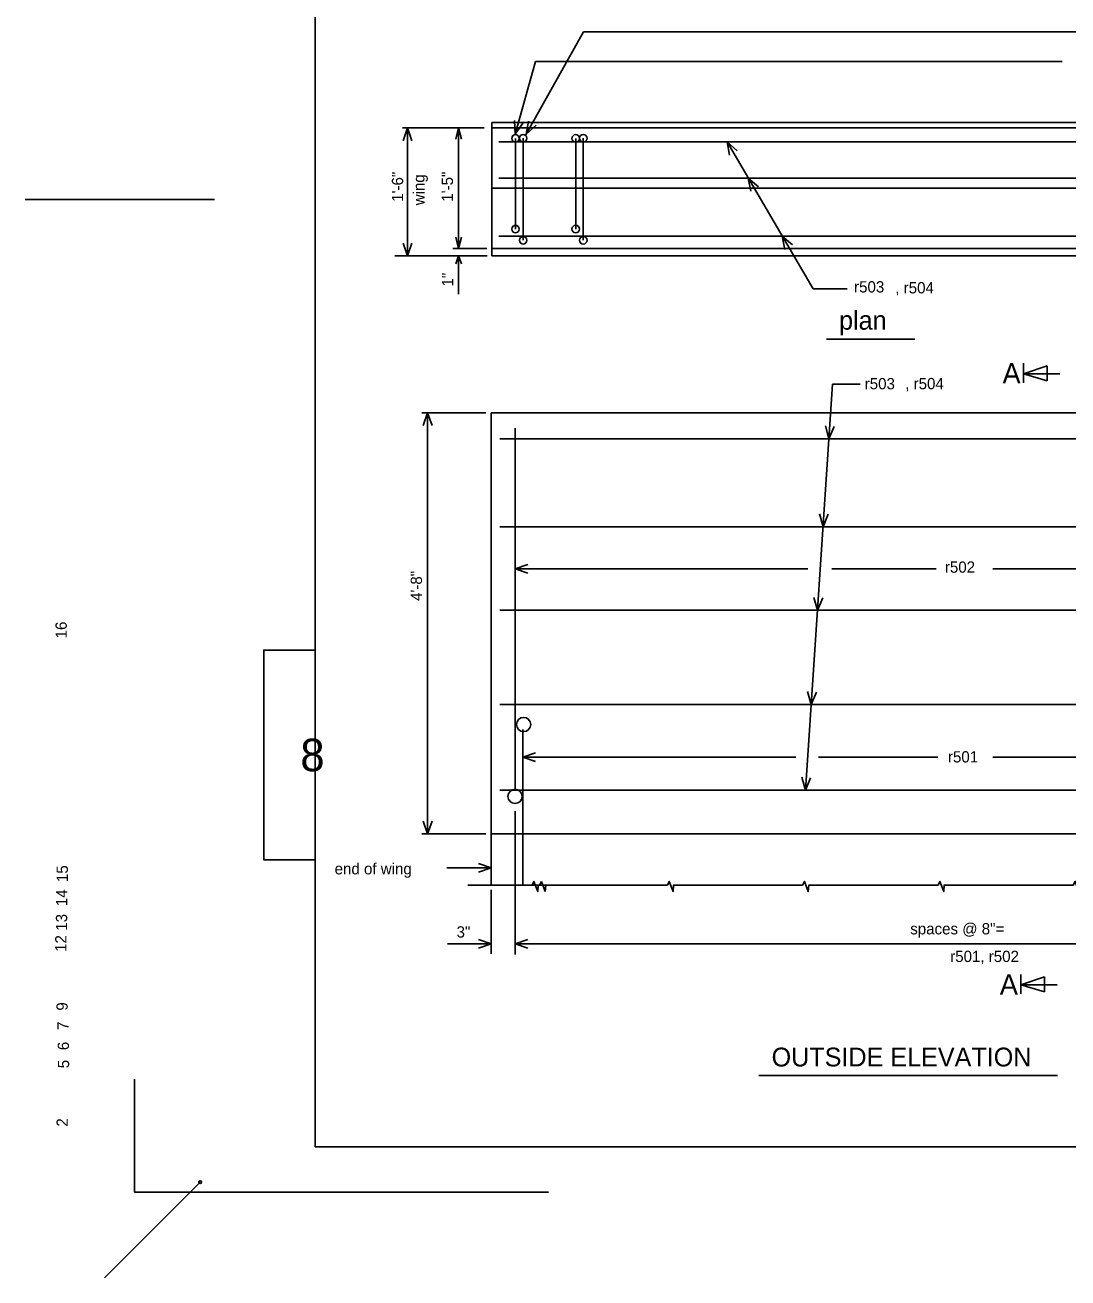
# Model space of a CAD drawing. Extents: x -81 to -44.8, y 85.9 to 111.1.
# Drawn here: x -81.01 to -69.45, y 86.74 to 100.62 of the extents above; entities that cross this region are included whole.
import ezdxf

# ---------------------------------------------------------------- set-up
doc = ezdxf.new("R2010")
doc.units = 0
for name, color, linetype in [('Level 1', 7, 'Continuous'), ('Level 12', 7, 'Continuous'), ('Level 13', 7, 'Continuous'), ('Level 14', 7, 'Continuous'), ('Level 15', 7, 'Continuous'), ('Level 16', 7, 'Continuous'), ('Level 2', 7, 'Continuous'), ('Level 37', 7, 'Continuous'), ('Level 49', 7, 'Continuous'), ('Level 5', 7, 'Continuous'), ('Level 6', 7, 'Continuous'), ('Level 7', 7, 'Continuous'), ('Level 9', 7, 'Continuous')]:
    doc.layers.add(name, color=color, linetype=linetype)

msp = doc.modelspace()

# ---------------------------------------------------------------- linework, layer by layer
at = {"layer": 'Level 1'}
for p, q in [((-77.797, 88.192), (-77.797, 109.192)), ((-76.156, 99.483), (-76.269, 99.483)), ((-76.206, 99.483), (-76.206, 98.149)), ((-75.895, 98.149), (-76.269, 98.149)), ((-79.797, 88.944), (-79.797, 87.692)), ((-77.797, 88.192), (-46.422, 88.192)), ((-79.797, 87.692), (-75.209, 87.692))]:
    msp.add_line(p, q, dxfattribs=at)
for points in [[(-76.238, 99.358), (-76.206, 99.483), (-76.175, 99.358)], [(-76.175, 98.274), (-76.206, 98.149), (-76.238, 98.274)]]:
    msp.add_lwpolyline(points, dxfattribs=at)
msp.add_lwpolyline([(-77.797, 93.697), (-78.365, 93.697), (-78.365, 91.375), (-77.797, 91.375)], close=True, dxfattribs=at)
at = {"layer": 'Level 2'}
for p, q in [((-76.206, 98.066), (-76.206, 97.642)), ((-80.129, 86.74), (-79.069, 87.801))]:
    msp.add_line(p, q, dxfattribs=at)
msp.add_lwpolyline([(-76.237, 97.978), (-76.206, 98.066), (-76.176, 97.978)], dxfattribs=at)
at = {"layer": 'Level 37'}
msp.add_line((-78.912, 98.692), (-81.011, 98.692), dxfattribs=at)
at = {"layer": 'Level 49'}
msp.add_circle((-79.069, 87.801), 0.0152, dxfattribs=at)
at = {"layer": 'Level 5'}
for p, q in [((-75.457, 99.413), (-74.821, 100.55)), ((-74.821, 100.55), (-69.231, 100.55)), ((-75.579, 99.416), (-75.355, 100.22)), ((-75.355, 100.22), (-75.092, 100.22)), ((-75.355, 100.22), (-69.518, 100.22)), ((-65.333, 99.545), (-75.839, 99.545)), ((-75.839, 98.149), (-75.839, 99.545)), ((-75.922, 99.483), (-76.829, 99.483)), ((-76.772, 98.066), (-76.772, 99.483)), ((-65.333, 99.483), (-75.839, 99.483)), ((-65.333, 99.328), (-75.762, 99.328)), ((-75.576, 99.368), (-75.576, 98.363)), ((-75.491, 99.369), (-75.491, 98.238)), ((-74.909, 99.368), (-74.909, 98.363)), ((-74.825, 99.369), (-74.825, 98.238)), ((-65.333, 98.928), (-75.762, 98.928)), ((-65.333, 98.816), (-75.839, 98.816)), ((-75.762, 98.284), (-65.333, 98.284)), ((-75.889, 98.066), (-76.913, 98.066)), ((-75.839, 98.066), (-75.839, 98.149)), ((-65.333, 98.149), (-75.839, 98.149)), ((-65.333, 98.066), (-75.839, 98.066)), ((-72.13, 97.143), (-71.152, 97.143)), ((-69.947, 96.876), (-69.947, 96.66)), ((-69.947, 96.759), (-69.683, 96.847)), ((-69.683, 96.847), (-69.683, 96.682)), ((-72.364, 92.144), (-72.062, 96.645)), ((-72.062, 96.645), (-71.756, 96.645)), ((-69.683, 96.682), (-69.947, 96.759)), ((-69.947, 96.759), (-69.543, 96.759)), ((-75.906, 96.328), (-76.612, 96.328)), ((-76.55, 96.328), (-76.55, 91.661)), ((-75.844, 96.328), (-75.844, 91.093)), ((-75.844, 96.328), (-65.352, 96.328)), ((-75.581, 96.155), (-75.581, 92.144)), ((-65.352, 96.039), (-75.749, 96.039)), ((-65.352, 95.065), (-75.749, 95.065)), ((-75.581, 94.597), (-72.335, 94.597)), ((-72.071, 94.597), (-70.914, 94.597)), ((-70.285, 94.597), (-65.352, 94.597)), ((-65.352, 94.138), (-75.749, 94.138)), ((-65.352, 93.095), (-75.749, 93.095)), ((-75.496, 92.816), (-75.496, 91.093)), ((-75.496, 92.51), (-72.468, 92.51)), ((-72.22, 92.51), (-70.897, 92.51)), ((-70.285, 92.51), (-65.352, 92.51)), ((-65.352, 92.144), (-75.749, 92.144)), ((-75.581, 91.911), (-75.581, 90.326)), ((-75.906, 91.661), (-76.612, 91.661)), ((-75.844, 91.661), (-65.352, 91.661)), ((-76.337, 91.284), (-75.844, 91.284)), ((-76.1, 91.093), (-75.309, 91.093)), ((-75.309, 91.093), (-75.288, 91.134)), ((-75.288, 91.134), (-75.246, 91.022)), ((-75.246, 91.022), (-75.24, 91.093)), ((-75.844, 91.042), (-75.844, 90.331)), ((-76.33, 90.443), (-75.844, 90.443)), ((-75.581, 90.443), (-64.05, 90.443)), ((-69.977, 90.104), (-69.977, 89.888)), ((-69.977, 89.987), (-69.714, 90.075)), ((-69.714, 89.91), (-69.977, 89.987)), ((-69.977, 89.987), (-69.573, 89.987)), ((-69.714, 90.075), (-69.714, 89.91)), ((-72.881, 88.983), (-69.57, 88.983)), ((-72.881, 88.983), (-69.57, 88.983))]:
    msp.add_line(p, q, dxfattribs=at)
for points in [[(-75.494, 99.538), (-75.579, 99.416), (-75.588, 99.565)], [(-75.346, 99.513), (-75.457, 99.413), (-75.431, 99.56)], [(-76.821, 99.342), (-76.772, 99.483), (-76.723, 99.342)], [(-73.232, 99.328), (-72.277, 97.7), (-71.901, 97.7)], [(-73.203, 99.181), (-73.232, 99.328), (-73.119, 99.231)], [(-72.968, 98.782), (-72.998, 98.928), (-72.884, 98.831)], [(-76.723, 98.207), (-76.772, 98.066), (-76.821, 98.207)], [(-72.591, 98.138), (-72.62, 98.284), (-72.507, 98.188)], [(-76.598, 96.187), (-76.55, 96.328), (-76.501, 96.187)], [(-72.045, 96.176), (-72.103, 96.039), (-72.142, 96.183)], [(-72.11, 95.202), (-72.168, 95.065), (-72.207, 95.209)], [(-75.44, 94.548), (-75.581, 94.597), (-75.44, 94.646)], [(-72.172, 94.275), (-72.23, 94.138), (-72.269, 94.282)], [(-72.242, 93.232), (-72.3, 93.095), (-72.339, 93.238)], [(-75.356, 92.462), (-75.496, 92.51), (-75.356, 92.559)], [(-72.306, 92.281), (-72.364, 92.144), (-72.403, 92.288)], [(-76.501, 91.802), (-76.55, 91.661), (-76.598, 91.802)], [(-75.985, 91.333), (-75.844, 91.284), (-75.985, 91.235)], [(-76.105, 91.093), (-75.393, 91.093), (-75.371, 91.134), (-75.33, 91.022), (-75.324, 91.093), (-74.605, 91.093)], [(-74.605, 91.093), (-73.893, 91.093), (-73.872, 91.134), (-73.83, 91.022), (-73.824, 91.093), (-73.106, 91.093)], [(-73.106, 91.093), (-72.394, 91.093), (-72.372, 91.134), (-72.331, 91.022), (-72.325, 91.093), (-71.607, 91.093)], [(-71.607, 91.093), (-70.894, 91.093), (-70.873, 91.134), (-70.831, 91.022), (-70.826, 91.093), (-70.107, 91.093)], [(-70.107, 91.093), (-69.395, 91.093), (-69.373, 91.134), (-69.332, 91.022), (-69.326, 91.093), (-68.359, 91.093)], [(-75.985, 90.491), (-75.844, 90.443), (-75.985, 90.394)], [(-75.44, 90.394), (-75.581, 90.443), (-75.44, 90.491)]]:
    msp.add_lwpolyline(points, dxfattribs=at)
for centre, radius in [((-75.576, 99.368), 0.0417), ((-75.491, 99.369), 0.0417), ((-74.909, 99.368), 0.0417), ((-74.825, 99.369), 0.0417), ((-75.576, 98.363), 0.0417), ((-74.909, 98.363), 0.0417), ((-75.491, 98.238), 0.0417), ((-74.825, 98.238), 0.0417), ((-75.486, 92.873), 0.0788), ((-75.581, 92.076), 0.0788)]:
    msp.add_circle(centre, radius, dxfattribs=at)

# ---------------------------------------------------------------- texts
at = {"layer": 'Level 1'}
for s, p in [('1\'-5"', (-76.269, 98.666)), ('1"', (-76.265, 97.726))]:
    msp.add_text(s, height=0.125, rotation=90, dxfattribs=at).set_placement(p)
msp.add_text('8', height=0.361, dxfattribs=at).set_placement((-77.96, 92.355))
at = {"layer": 'Level 12'}
msp.add_text('12', height=0.125, rotation=90, dxfattribs=at).set_placement((-80.552, 90.353))
at = {"layer": 'Level 13'}
msp.add_text('13', height=0.125, rotation=90, dxfattribs=at).set_placement((-80.544, 90.588))
at = {"layer": 'Level 14'}
msp.add_text('14', height=0.125, rotation=90, dxfattribs=at).set_placement((-80.542, 90.86))
at = {"layer": 'Level 15'}
msp.add_text('15', height=0.125, rotation=90, dxfattribs=at).set_placement((-80.536, 91.127))
at = {"layer": 'Level 16'}
for p in [(-71.367, 97.65), (-71.257, 96.588)]:
    msp.add_text(', r504', height=0.125, dxfattribs=at).set_placement(p)
msp.add_text('16', height=0.125, rotation=90, dxfattribs=at).set_placement((-80.548, 93.827))
at = {"layer": 'Level 2'}
msp.add_text('2', height=0.125, rotation=90, dxfattribs=at).set_placement((-80.537, 88.417))
at = {"layer": 'Level 5'}
for s, p in [('1\'-6"', (-76.821, 98.665)), ('wing', (-76.584, 98.626)), ('4\'-8"', (-76.612, 94.242)), ('5', (-80.522, 89.064))]:
    msp.add_text(s, height=0.125, rotation=90, dxfattribs=at).set_placement(p)
for s, height, p in [('r503', 0.125, (-71.824, 97.66)), ('plan', 0.2083, (-71.99, 97.248)), ('A', 0.225, (-70.179, 96.652)), ('r503', 0.125, (-71.706, 96.587)), ('r502', 0.125, (-70.818, 94.555)), ('r501', 0.125, (-70.784, 92.452)), ('end of wing', 0.125, (-77.58, 91.212)), ('   spaces @ 8"=        ', 0.125, (-71.341, 90.547)), ('3"', 0.125, (-76.229, 90.512)), ('r501, r502', 0.125, (-70.759, 90.241)), ('A', 0.225, (-70.209, 89.88)), ('OUTSIDE ELEVATION', 0.20834, (-72.738, 89.084)), ('OUTSIDE ELEVATION', 0.20834, (-72.738, 89.084))]:
    msp.add_text(s, height=height, dxfattribs=at).set_placement(p)
at = {"layer": 'Level 6'}
msp.add_text('6', height=0.125, rotation=90, dxfattribs=at).set_placement((-80.524, 89.264))
at = {"layer": 'Level 7'}
msp.add_text('7', height=0.125, rotation=90, dxfattribs=at).set_placement((-80.527, 89.488))
at = {"layer": 'Level 9'}
msp.add_text('9', height=0.125, rotation=90, dxfattribs=at).set_placement((-80.538, 89.702))

doc.saveas('drawing.dxf')
